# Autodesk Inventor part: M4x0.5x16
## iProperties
Created: 2014-07
Part Number: M4x0.5x16
Material: 강, 연강
Description: 6각머리 태핑 나사
Document SubType Name: Modeling
Standard: KS B 1003
Designer: KYOUNG IL JANG
Standards Organization: KS
Language: ko-KR
Size Designation: M 4 x 16
Categories: <MemberInstance><Categories><Category DisplayName="조임쇠" InternalName="e4da775c-781d-43d5-af7c-5136215cf5a6" Mnemonic="FSTN"><Category DisplayName="볼트" InternalN
Density: 1 g/cm^3
Company: 한국ATC센터
IsCustomPart: 1
Author: KYOUNG IL JANG
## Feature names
1. Fillet2
